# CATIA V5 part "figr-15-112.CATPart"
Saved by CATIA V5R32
Part number: Part1
Bounding box of the stored display mesh (mm): x -55.37 to 68.649, y -21.457 to 35.984, z 0 to 57.441
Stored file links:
  D:\PROJECTS\Project 2022\CATIA V5 6R 2022\Resources\Part Files\c15_catia_v5_6r2022_prt\figr-15-112.CATPart
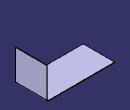
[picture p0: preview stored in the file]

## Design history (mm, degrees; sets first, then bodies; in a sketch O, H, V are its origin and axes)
SheetMetalParameters1: Thickness 1, BendRadius 2, KFactor 0.400515 {= log(min(100,max(20*SheetMetalParameters1.BendRadius,SheetMetalParameters1.Thickness)/SheetMetalParameters1.Thickness))/log(100)/2}, ReliefRadialLength 1, ReliefAxialLength 2, MinimumBendRadius 0
Body1 (main body)
  Sketch1 on xy-plane, origin (0, 0, 0), H (1, 0, 0), V (0, 1, 0)
    line L1 (-55.3695, 35.9836) -> (67.649, 35.9836)
    line L2 (67.649, 35.9836) -> (67.649, -21.4575)
    line L3 (67.649, -21.4575) -> (-55.3695, -21.4575)
    line L4 (-55.3695, -21.4575) -> (-55.3695, 35.9836)
    horizontal: L1 H, L3 H
    vertical: L2 V, L4 V
  Wall1: Thickness 1, Profile Sketch1
  d_NewWallOnEdge1: NewWallOnEdge_Edge edge [face of Wall1 | face of Wall1], NewWallOnEdge_Length 57.4411, NewWallOnEdge_HeightLimitOffset 0, NewWallOnEdge_WidthOffset1 0, NewWallOnEdge_WidthOffset2 0, NewWallOnEdge_Angle 90, NewWallOnEdge_BendRadiusValue 2 {= SheetMetalParameters1.BendRadius}, NewWallOnEdge_BendTable SheetMetalParameters1, KFacteur 0.400515 {= log(min(100,max(20*d_NewWallOnEdge1.Radius,SheetMetalParameters1.Thickness)/SheetMetalParameters1.Thickness))/log(100)/2}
